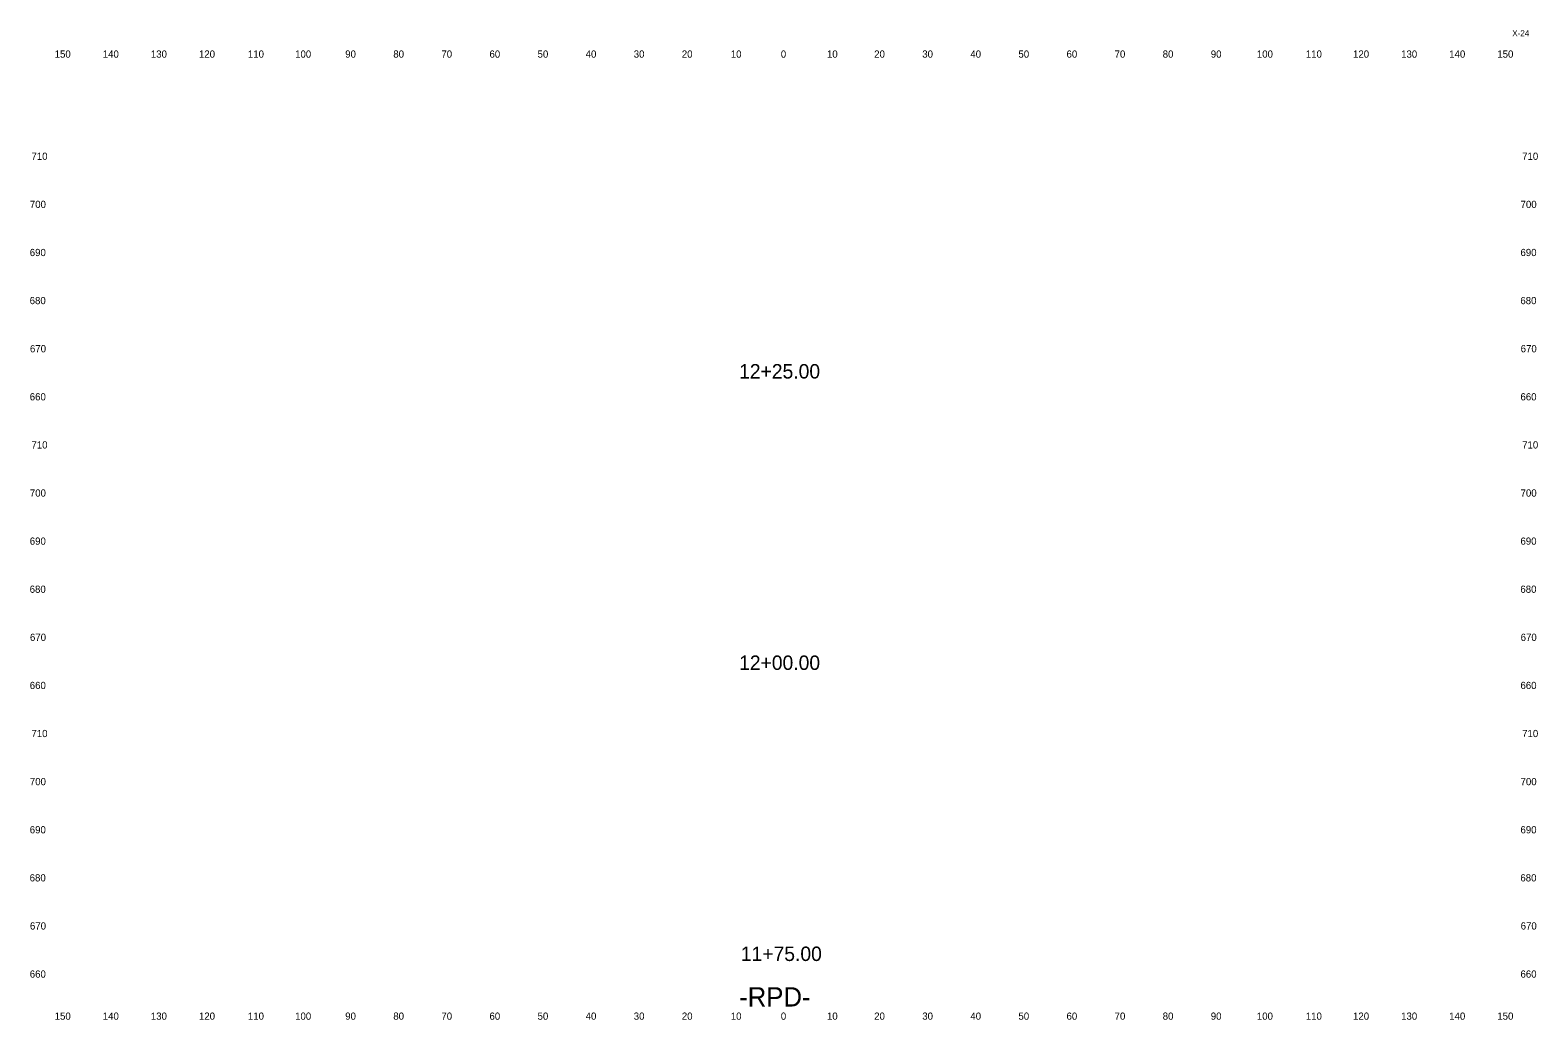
# Model space of a CAD drawing. Extents: x 3 to 317, y 1 to 867.
# Drawn here: x 3.3 to 316.9, y 221.2 to 427 of the extents above; entities that cross this region are included whole.
import ezdxf

# ---------------------------------------------------------------- set-up
doc = ezdxf.new("R2010")
doc.units = 0
for name, color, linetype in [('Prop XS Alignment Label', 7, 'Continuous'), ('Prop XS Elevation Labels', 7, 'Continuous'), ('Prop XS Offset Labels', 7, 'Continuous'), ('Prop XS Sheet Number', 7, 'Continuous'), ('Prop XS Station Labels', 7, 'Continuous')]:
    doc.layers.add(name, color=color, linetype=linetype)

msp = doc.modelspace()

# ---------------------------------------------------------------- texts
at = {"layer": 'Prop XS Alignment Label'}
msp.add_text('-RPD-', height=4, dxfattribs=at).set_placement((150.78, 224))
at = {"layer": 'Prop XS Elevation Labels'}
for s, p in [('710', (3.61, 400)), ('710', (313.61, 400)), ('700', (3.28, 390)), ('700', (313.28, 390)), ('690', (3.26, 380)), ('690', (313.26, 380)), ('680', (3.24, 370)), ('680', (313.24, 370)), ('670', (3.3, 360)), ('670', (313.3, 360)), ('660', (3.26, 350)), ('660', (313.26, 350)), ('710', (3.61, 340)), ('710', (313.61, 340)), ('700', (3.28, 330)), ('700', (313.28, 330)), ('690', (3.26, 320)), ('690', (313.26, 320)), ('680', (3.24, 310)), ('680', (313.24, 310)), ('670', (3.3, 300)), ('670', (313.3, 300)), ('660', (3.26, 290)), ('660', (313.26, 290)), ('710', (3.61, 280)), ('710', (313.61, 280)), ('700', (3.28, 270)), ('700', (313.28, 270)), ('690', (3.26, 260)), ('690', (313.26, 260)), ('680', (3.24, 250)), ('680', (313.24, 250)), ('670', (3.3, 240)), ('670', (313.3, 240)), ('660', (3.26, 230)), ('660', (313.26, 230))]:
    msp.add_text(s, height=1.5, dxfattribs=at).set_placement(p)
at = {"layer": 'Prop XS Offset Labels'}
for s, p in [('150', (8.44, 421.25)), ('140', (18.44, 421.25)), ('130', (28.44, 421.25)), ('120', (38.44, 421.25)), ('110', (48.62, 421.25)), ('100', (58.44, 421.25)), ('90', (68.86, 421.25)), ('80', (78.86, 421.25)), ('70', (88.86, 421.25)), ('60', (98.86, 421.25)), ('50', (108.86, 421.25)), ('40', (118.86, 421.25)), ('30', (128.86, 421.25)), ('20', (138.86, 421.25)), ('10', (149.04, 421.25)), ('0', (159.45, 421.25)), ('10', (169.04, 421.25)), ('20', (178.86, 421.25)), ('30', (188.86, 421.25)), ('40', (198.86, 421.25)), ('50', (208.86, 421.25)), ('60', (218.86, 421.25)), ('70', (228.86, 421.25)), ('80', (238.86, 421.25)), ('90', (248.86, 421.25)), ('100', (258.44, 421.25)), ('110', (268.62, 421.25)), ('120', (278.44, 421.25)), ('130', (288.44, 421.25)), ('140', (298.44, 421.25)), ('150', (308.44, 421.25)), ('150', (8.44, 221.25)), ('140', (18.44, 221.25)), ('130', (28.44, 221.25)), ('120', (38.44, 221.25)), ('110', (48.62, 221.25)), ('100', (58.44, 221.25)), ('90', (68.86, 221.25)), ('80', (78.86, 221.25)), ('70', (88.86, 221.25)), ('60', (98.86, 221.25)), ('50', (108.86, 221.25)), ('40', (118.86, 221.25)), ('30', (128.86, 221.25)), ('20', (138.86, 221.25)), ('10', (149.04, 221.25)), ('0', (159.45, 221.25)), ('10', (169.04, 221.25)), ('20', (178.86, 221.25)), ('30', (188.86, 221.25)), ('40', (198.86, 221.25)), ('50', (208.86, 221.25)), ('60', (218.86, 221.25)), ('70', (228.86, 221.25)), ('80', (238.86, 221.25)), ('90', (248.86, 221.25)), ('100', (258.44, 221.25)), ('110', (268.62, 221.25)), ('120', (278.44, 221.25)), ('130', (288.44, 221.25)), ('140', (298.44, 221.25)), ('150', (308.44, 221.25))]:
    msp.add_text(s, height=1.5, dxfattribs=at).set_placement(p)
at = {"layer": 'Prop XS Sheet Number'}
msp.add_text('X-24', height=1.25, dxfattribs=at).set_placement((311.56, 425.7))
at = {"layer": 'Prop XS Station Labels'}
for s, p in [('12+25.00', (150.77, 354.55)), ('12+00.00', (150.77, 293.97)), ('11+75.00', (151.13, 233.46))]:
    msp.add_text(s, height=3, dxfattribs=at).set_placement(p)

doc.saveas('drawing.dxf')
